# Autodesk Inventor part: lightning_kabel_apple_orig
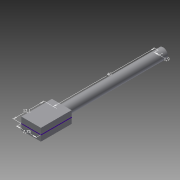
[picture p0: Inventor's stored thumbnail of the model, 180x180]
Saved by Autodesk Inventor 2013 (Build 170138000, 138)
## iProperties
Created: 2013-04
Part Number: lightning_kabel_apple_orig
Material: Allgemein
Document SubType Name: Modeling
Designer: md
Density: 1 g/cm^3
Author: md
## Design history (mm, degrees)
sketch "Skizze1"
  geometry: L1 (-3.875, -6.05)-(3.875, -6.05); L2 (3.875, -6.05)-(3.875, 6.05); L3 (3.875, 6.05)-(-3.875, 6.05); L4 (-3.875, 6.05)-(-3.875, -6.05); L5 (-3.875, -6.05)-(3.875, 6.05); L6 (3.875, -6.05)-(-3.875, 6.05); L7 (1.9, -6.05)-(-1.9, -6.05); L8 (0, 6.05)-(0, -46.05); L9 (0, -46.05)-(1.9, -46.05); L10 (1.9, -46.05)-(1.9, -6.05); L11 (1.9, -6.05)-(0, -6.05); L12 (0, -6.05)-(0, -46.05); 3 further points
  constraints: 24 end point, 4 parallel, 3 midpoint, 2 horizontal, 2 perpendicular, 2 point on line
  dimensions: "d0" = 7.75 distance between parallel lines of L2 L4; "d2" = 12.1 distance of L1.end L2.end; "d6" = 1.9 distance of L8.end L9.end; "d10" = 40 distance of L9.end L7.start
revolve "Umdrehung1" stored, may be unused: angle "d7" = 90 deg
extrude "Extrusion1" join sketch "Skizze1" stored distance "d8" = 4.7; taper "d9" = 0 deg
node "Volumenkörper1"
